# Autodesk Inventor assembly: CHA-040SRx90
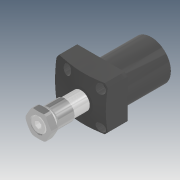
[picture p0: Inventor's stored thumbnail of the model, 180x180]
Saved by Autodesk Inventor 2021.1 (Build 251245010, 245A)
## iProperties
Created: 2019-05
Part Number: CHA-040SRx90
Description: STEP AP203
Document SubType Name: Assembly
Designer: user
Sending System: SolidWorks 2017
Preprocessor: SwSTEP 2.0
Title: CHA-040SRx90.STEP
Revision Number: ÈÎºÎ
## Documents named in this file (5)
- D:\Vault_2016\Projekty\Clamptek\Hydraulic\CHA\CHA\CHA-040\Inventor\CHA-040SRx90\CHA-040SRx90.iam
- D:\Vault_2016\Projekty\Clamptek\Hydraulic\CHA\CHA\CHA-040\Inventor\CHA-040SRx90\CHA-040±¾Ìå.ipt
- D:\Vault_2016\Projekty\Clamptek\Hydraulic\CHA\CHA\CHA-040\Inventor\CHA-040SRx90\CHA-040S»îÈû¸Ë.ipt
- D:\Vault_2016\Projekty\Clamptek\Hydraulic\CHA\CHA\CHA-040\Inventor\CHA-040SRx90\CHA-040S×¶Ì×.ipt
- D:\Vault_2016\Projekty\Clamptek\Hydraulic\CHA\CHA\CHA-040\Inventor\CHA-040SRx90\CHA-040ÂÝÄ¸.ipt
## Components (4 placed, 4 different names)
1. CHA-040±¾Ìå_1
2. CHA-040S»îÈû¸Ë_2
3. CHA-040S×¶Ì×_3
4. CHA-040ÂÝÄ¸_4
